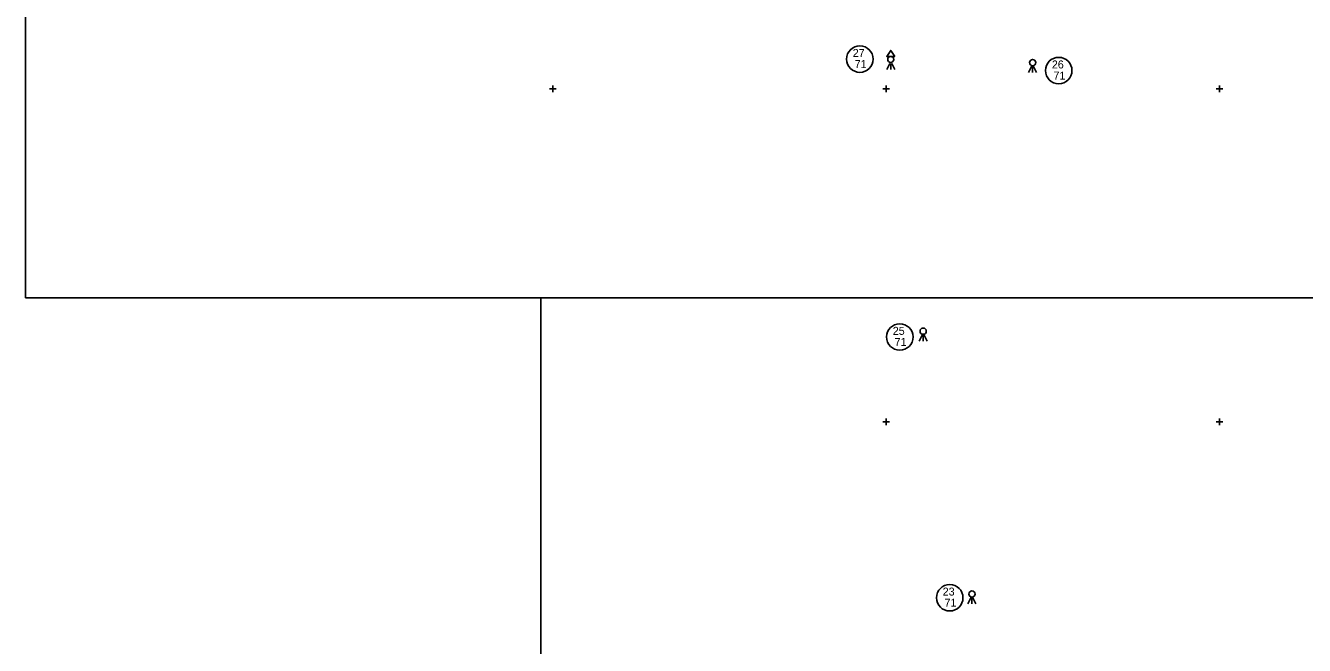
# Model space of a CAD drawing. Extents: x -597440 to -597210, y -1158961 to -1158436.
# Drawn here: x -597439.5 to -597343.6, y -1158566.8 to -1158520.3 of the extents above; entities that cross this region are included whole.
import ezdxf

# ---------------------------------------------------------------- set-up
doc = ezdxf.new("R2010")
doc.units = 0
for name, color, linetype in [('Vrstva 1', 7, 'Continuous'), ('Vrstva 44', 7, 'Continuous'), ('Vrstva 45', 7, 'Continuous'), ('Vrstva 62', 7, 'Continuous')]:
    doc.layers.add(name, color=color, linetype=linetype)

msp = doc.modelspace()

# ---------------------------------------------------------------- linework, layer by layer
at = {"layer": 'Vrstva 1'}
for points in [[(-597439.544, -1158540.686), (-597291.044, -1158540.686), (-597291.044, -1158435.686), (-597439.544, -1158435.686)], [(-597400.897, -1158750.686), (-597252.397, -1158750.686), (-597252.397, -1158540.686), (-597400.897, -1158540.686)]]:
    msp.add_lwpolyline(points, close=True, dxfattribs=at)
at = {"layer": 'Vrstva 44'}
for p, q in [((-597374.736, -1158523.093), (-597374.961, -1158523.543)), ((-597374.661, -1158523.093), (-597374.661, -1158523.543)), ((-597374.586, -1158523.093), (-597374.361, -1158523.543)), ((-597364.089, -1158523.324), (-597364.315, -1158523.776)), ((-597364.015, -1158523.326), (-597364.015, -1158523.776)), ((-597363.94, -1158523.324), (-597363.715, -1158523.776)), ((-597372.3, -1158543.483), (-597372.526, -1158543.935)), ((-597372.226, -1158543.485), (-597372.226, -1158543.935)), ((-597372.151, -1158543.483), (-597371.926, -1158543.935)), ((-597368.642, -1158563.21), (-597368.868, -1158563.662)), ((-597368.568, -1158563.212), (-597368.568, -1158563.662)), ((-597368.493, -1158563.21), (-597368.268, -1158563.662))]:
    msp.add_line(p, q, dxfattribs=at)
msp.add_lwpolyline([(-597374.358, -1158522.569), (-597374.96, -1158522.569), (-597374.661, -1158522.112)], close=True, dxfattribs=at)
for centre, radius in [((-597374.661, -1158522.793), 0.224), ((-597364.015, -1158523.031), 0.234), ((-597372.226, -1158543.19), 0.234), ((-597368.568, -1158562.917), 0.234)]:
    msp.add_circle(centre, radius, dxfattribs=at)
at = {"layer": 'Vrstva 45'}
for centre in [(-597376.973, -1158522.768), (-597362.06, -1158523.63), (-597373.977, -1158543.624), (-597370.232, -1158563.192)]:
    msp.add_circle(centre, 0.994, dxfattribs=at)
at = {"layer": 'Vrstva 62'}
for p, q in [((-597400.25, -1158525), (-597399.75, -1158525)), ((-597400, -1158524.75), (-597400, -1158525.25)), ((-597375.25, -1158525), (-597374.75, -1158525)), ((-597375, -1158524.75), (-597375, -1158525.25)), ((-597350.25, -1158525), (-597349.75, -1158525)), ((-597350, -1158524.75), (-597350, -1158525.25)), ((-597375.25, -1158550), (-597374.75, -1158550)), ((-597375, -1158549.75), (-597375, -1158550.25)), ((-597350.25, -1158550), (-597349.75, -1158550)), ((-597350, -1158549.75), (-597350, -1158550.25))]:
    msp.add_line(p, q, dxfattribs=at)

# ---------------------------------------------------------------- texts
at = {"layer": 'Vrstva 45'}
for s, p in [('27', (-597377.505, -1158522.608)), ('71', (-597377.364, -1158523.442)), ('26', (-597362.573, -1158523.47)), ('71', (-597362.451, -1158524.304)), ('25', (-597374.504, -1158543.464)), ('71', (-597374.368, -1158544.298)), ('23', (-597370.759, -1158563.032)), ('71', (-597370.623, -1158563.866))]:
    msp.add_text(s, height=0.6, dxfattribs=at).set_placement(p)

doc.saveas('drawing.dxf')
